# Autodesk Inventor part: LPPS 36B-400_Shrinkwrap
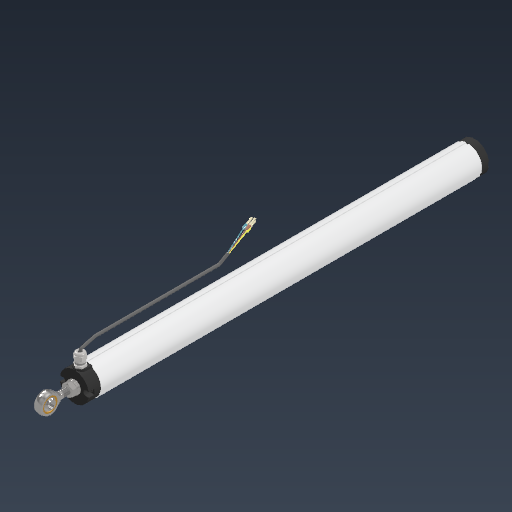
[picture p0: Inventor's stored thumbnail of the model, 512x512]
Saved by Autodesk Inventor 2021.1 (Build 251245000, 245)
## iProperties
Created: 2020-09
Part Number: LPPS 36B-400_Shrinkwrap
Material: Generic
Document SubType Name: Modeling
Designer: J. Nielson
Density: 1 g/cm^3
Appearance: Default
Author: J. Nielson
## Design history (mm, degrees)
derived "LPPS 36B-400.iam"
body "Solid1"
node "LPPS 36B Cable End Cap.iam:1::LPPS-36B PLASTIC CABLE END.ipt"
node "LPPS 36B Cable End Cap.iam:1::LPPS 36B- Cable Gland.ipt:1"
body "Solid2"
node "LPPS 36B Cable End Cap.iam:1::Cable Gland Cap.ipt:1"
body "Solid3"
node "LPPS 36B Cable End Cap.iam:1::Cable.ipt:1"
body "Solid4"
node "LPPS 36B Cable End Cap.iam:1::Cable Gland Seal 1 of 2.ipt:1"
body "Solid5"
node "LPPS 36B Cable End Cap.iam:1::Cable Gland 2 of 2.ipt:1"
body "Solid6"
node "LPPS 36B Cable End Cap.iam:1::#6 Terminal Ring 22 - 18 AWG.i"
body "Solid7"
node "LPPS-36-400 METAL HOUSING.ipt:1"
body "Solid8"
node "MALE Rod Eye SW.ipt:1"
body "Solid9"
node "LPPS-36B PLASTIC STROKE END.ipt:1"
body "Solid10"
node "LPPS 36B-400 Back Stop.ipt:1"
body "Solid11"
node "LPPS 36B-400 Front Stop.ipt:1"
body "Solid12"
node "AS 1427 - M3 x 16.ipt:1"
body "Solid13"
node "AS 1427 - M3 x 16.ipt:2"
body "Solid14"
node "AS 1427 - M3 x 16.ipt:3"
body "Solid15"
node "AS 1427 - M3 x 16.ipt:4"
body "Solid16"
node "AS 1112 - M8  Type 5.ipt:1"
body "Solid17"
node "AS 1968 - 1976 - 8.ipt:1"
body "Solid18"
node "AS 1237 - 8.ipt:1"
body "Solid19"
